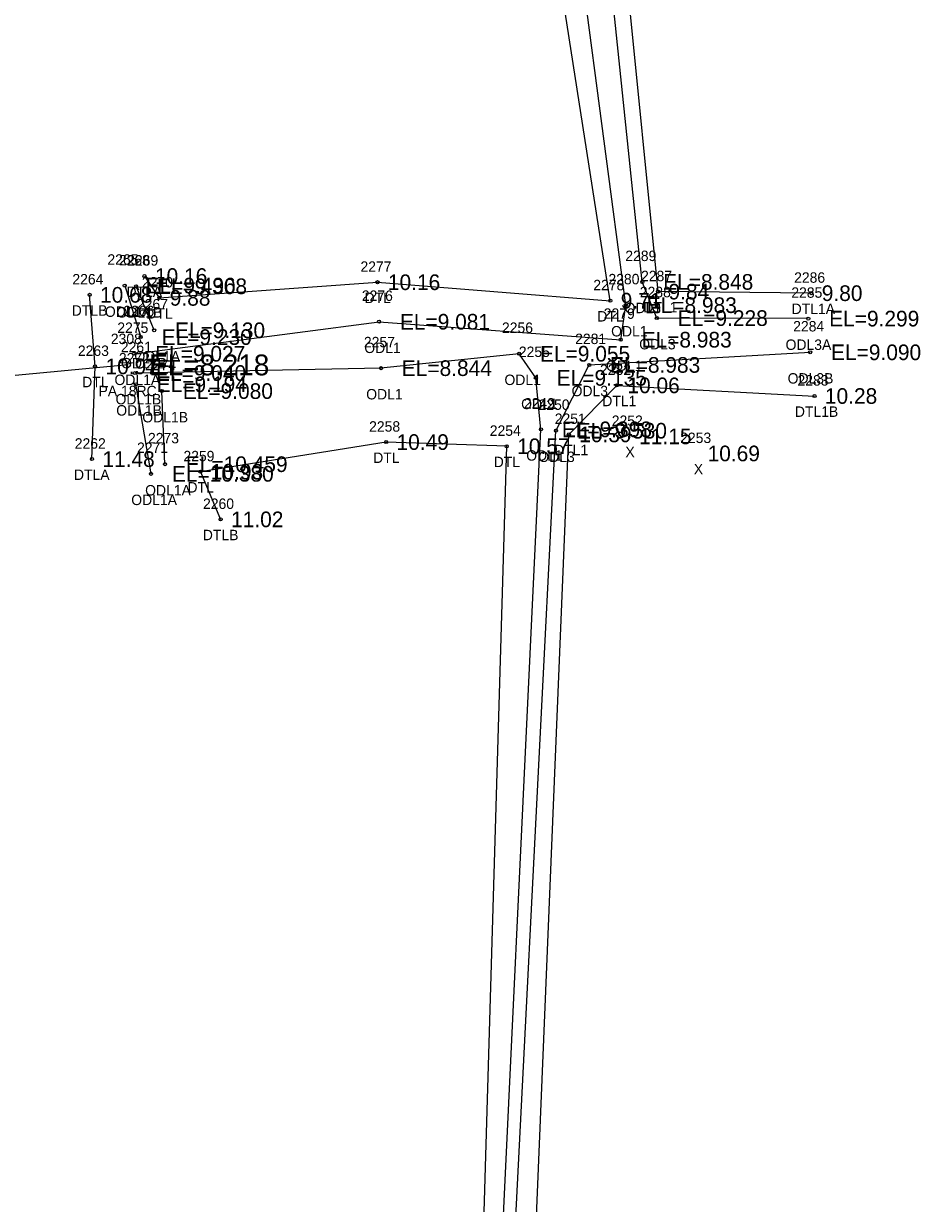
# Model space of a CAD drawing. Extents: x 2042117 to 2045853, y 303080 to 309569.
# Drawn here: x 2044366.1 to 2044452.1, y 305003.7 to 305116.8 of the extents above; entities that cross this region are included whole.
import ezdxf

# ---------------------------------------------------------------- set-up
doc = ezdxf.new("R2010")
doc.units = 0
for name, color, linetype in [('RD_EX_DR_Pipe', 7, 'Continuous'), ('RD_EX_DR_Pipe_txCode', 7, 'Continuous'), ('RD_EX_H2O', 7, 'Continuous'), ('RD_EX_H2O_txCode', 7, 'Continuous'), ('RD_EX_Misc_txCode', 7, 'Continuous'), ('RD_EX_TX_H2O_ELEV', 7, 'Continuous'), ('RD_EX_TX_Misc_ELEV', 7, 'Continuous'), ('RD_SMD_Locator', 7, 'Continuous'), ('RD_TX_Pipe_ElevEX', 7, 'Continuous')]:
    doc.layers.add(name, color=color, linetype=linetype)

msp = doc.modelspace()

# ---------------------------------------------------------------- linework, layer by layer
at = {"layer": 'RD_EX_DR_Pipe'}
msp.add_line((2044376.14, 305084.11), (2044342.61, 305081.01), dxfattribs=at)
at = {"layer": 'RD_EX_H2O'}
for p, q in [((2044375.8, 305091.72), (2044377.34, 305086.78)), ((2044378.62, 305087.43), (2044376.89, 305091.65)), ((2044378.33, 305073.67), (2044376.87, 305082.25)), ((2044379.66, 305074.59), (2044379.37, 305081.6))]:
    msp.add_line(p, q, dxfattribs=at)
for points in [[(2044376.72, 305085.18), (2044400.19, 305088.25), (2044423.37, 305086.53), (2044423.86, 305089.84), (2044419.71, 305121.34), (2044421.53, 305178.54), (2044427.38, 305280.5)], [(2044441.36, 305088.55), (2044426.83, 305088.6), (2044425.44, 305092.07), (2044422.39, 305121.28), (2044424.49, 305178.48), (2044429.93, 305280.33)], [(2044441.65, 305090.99), (2044426.95, 305091.14), (2044423.93, 305121.62), (2044425.7, 305178.46), (2044431.41, 305280.23)], [(2044377.7, 305092.63), (2044379.12, 305090.54), (2044400.04, 305092.04), (2044422.37, 305090.27), (2044417.51, 305121.46), (2044420.43, 305178.33), (2044425.99, 305280.06)], [(2044372.66, 305075.08), (2044372.96, 305083.97), (2044372.43, 305090.83)], [(2044403.47, 304870.69), (2044407.44, 304869.96), (2044408.86, 304871.35), (2044409.24, 304878.26), (2044410.13, 304929), (2044410.94, 304977.69), (2044415.72, 305077.93), (2044415.23, 305082.87), (2044413.63, 305085.18), (2044400.37, 305083.8), (2044376.8, 305083.33)], [(2044412.68, 304824.61), (2044412.4, 304834.83), (2044410.65, 304865.22), (2044410.04, 304868.77), (2044410.66, 304878.11), (2044411.75, 304929.17), (2044412.06, 304977.88), (2044417.16, 305077.8), (2044420.35, 305084.11), (2044441.54, 305085.32)], [(2044415.25, 304826.5), (2044414.68, 304834.74), (2044412.57, 304868.88), (2044413.59, 304878.38), (2044413.66, 304929.44), (2044414.3, 304978.48), (2044418.39, 305077.45), (2044423.01, 305082.15), (2044441.95, 305081.13)], [(2044408.92, 304931.32), (2044409.54, 304978.02), (2044412.44, 305076.31), (2044400.87, 305076.71), (2044383.06, 305073.87), (2044385, 305069.3)]]:
    msp.add_lwpolyline(points, dxfattribs=at)
at = {"layer": 'RD_SMD_Locator'}
for centre, radius in [((2044377.7, 305092.63), 0.15), ((2044375.8, 305091.72), 0.15), ((2044376.89, 305091.65), 0.15), ((2044400.04, 305092.04), 0.15), ((2044425.44, 305092.07), 0.15), ((2044372.43, 305090.83), 0.15), ((2044379.12, 305090.54), 0.15), ((2044422.37, 305090.27), 0.15), ((2044426.95, 305091.14), 0.15), ((2044441.65, 305090.99), 0.15), ((2044423.86, 305089.84), 0.15), ((2044400.19, 305088.25), 0.15), ((2044426.83, 305088.6), 0.15), ((2044441.36, 305088.55), 0.15), ((2044377.34, 305086.78), 0.15), ((2044378.62, 305087.43), 0.15), ((2044423.37, 305086.53), 0.15), ((2044376.72, 305085.18), 0.15), ((2044413.63, 305085.18), 0.15), ((2044441.54, 305085.32), 0.15), ((2044372.96, 305083.97), 0.15), ((2044376.14, 305084.11), 0.2), ((2044376.8, 305083.33), 0.15), ((2044400.37, 305083.8), 0.15), ((2044420.35, 305084.11), 0.15), ((2044376.87, 305082.25), 0.15), ((2044415.23, 305082.87), 0.15), ((2044423.01, 305082.15), 0.15), ((2044379.37, 305081.6), 0.15), ((2044441.95, 305081.13), 0.15), ((2044415.72, 305077.93), 0.15), ((2044417.16, 305077.8), 0.15), ((2044400.87, 305076.71), 0.15), ((2044418.39, 305077.45), 0.15), ((2044412.44, 305076.31), 0.15), ((2044372.66, 305075.08), 0.15), ((2044379.66, 305074.59), 0.15), ((2044378.33, 305073.67), 0.15), ((2044383.06, 305073.87), 0.15), ((2044385, 305069.3), 0.15)]:
    msp.add_circle(centre, radius, dxfattribs=at)

# ---------------------------------------------------------------- texts
at = {"layer": 'RD_EX_DR_Pipe_txCode'}
for s, p in [('2308', (2044374.47, 305086.11)), ('PA 18RC', (2044373.29, 305081.11))]:
    msp.add_text(s, height=1, dxfattribs=at).set_placement(p)
at = {"layer": 'RD_EX_H2O_txCode'}
for s, p in [('2265', (2044374.14, 305093.72)), ('2289', (2044423.81, 305094.07)), ('2268', (2044375.24, 305093.65)), ('2269', (2044376.04, 305093.63)), ('2277', (2044398.41, 305093.04)), ('2264', (2044370.78, 305091.83)), ('2270', (2044377.45, 305091.54)), ('2280', (2044422.19, 305091.84)), ('2287', (2044425.32, 305092.14)), ('2286', (2044440, 305091.99)), ('DTLA', (2044375.97, 305090.63)), ('2278', (2044420.74, 305091.27)), ('2288', (2044425.2, 305090.6)), ('2285', (2044439.73, 305090.55)), ('2267', (2044376.97, 305089.43)), ('2276', (2044398.54, 305090.25)), ('DTL', (2044398.8, 305090.04)), ('DTLB', (2044370.72, 305088.83)), ('ODL1A', (2044373.9, 305088.72)), ('ODL1B', (2044375.01, 305088.65)), ('2266', (2044375.66, 305088.78)), ('DTL', (2044377.87, 305088.54)), ('DTL', (2044421.12, 305088.27)), ('2279', (2044421.74, 305088.53)), ('ODL3', (2044423.74, 305089.07)), ('DTL1', (2044425.54, 305089.14)), ('DTL1A', (2044439.76, 305088.99)), ('2275', (2044375.09, 305087.18)), ('2256', (2044411.98, 305087.18)), ('2284', (2044439.91, 305087.32)), ('2257', (2044398.74, 305085.8)), ('2281', (2044419, 305086.11)), ('ODL1', (2044422.45, 305086.84)), ('2263', (2044371.31, 305084.97)), ('2261', (2044375.43, 305085.33)), ('ODL1', (2044398.78, 305085.25)), ('2255', (2044413.6, 305084.87)), ('ODL3', (2044425.14, 305085.6)), ('ODL3A', (2044439.18, 305085.55)), ('2272', (2044375.24, 305084.25)), ('ODL1B', (2044375.45, 305083.78)), ('ODL1A', (2044376.73, 305084.43)), ('2274', (2044377.74, 305083.6)), ('ODL1', (2044421.96, 305083.53)), ('2282', (2044421.38, 305083.15)), ('DTL', (2044371.72, 305081.97)), ('ODL1A', (2044374.82, 305082.18)), ('ODL1', (2044412.22, 305082.18)), ('ODL3B', (2044439.38, 305082.32)), ('2283', (2044440.32, 305082.13)), ('ODL1B', (2044374.92, 305080.33)), ('ODL1', (2044398.96, 305080.8)), ('ODL3', (2044418.66, 305081.11)), ('DTL1', (2044421.6, 305080.15)), ('ODL1B', (2044374.99, 305079.25)), ('ODL1', (2044413.82, 305079.87)), ('2249', (2044414.09, 305079.93)), ('2250', (2044415.49, 305079.8)), ('DTL1B', (2044440.07, 305079.13)), ('ODL1B', (2044377.49, 305078.6)), ('2251', (2044417.04, 305078.45)), ('2258', (2044399.24, 305077.71)), ('2254', (2044410.81, 305077.31)), ('2262', (2044371.01, 305076.08)), ('2271', (2044376.98, 305075.67)), ('2273', (2044378.03, 305076.59)), ('2259', (2044381.43, 305074.87)), ('DTL', (2044399.63, 305074.71)), ('ODL1', (2044414.31, 305074.93)), ('ODL3', (2044415.47, 305074.8)), ('DTL1', (2044416.98, 305075.45)), ('DTL', (2044411.19, 305074.31)), ('DTLA', (2044370.93, 305073.08)), ('ODL1A', (2044377.76, 305071.59)), ('DTL', (2044381.82, 305071.87)), ('ODL1A', (2044376.43, 305070.67)), ('2260', (2044383.31, 305070.3)), ('DTLB', (2044383.29, 305067.3))]:
    msp.add_text(s, height=1, dxfattribs=at).set_placement(p)
at = {"layer": 'RD_EX_Misc_txCode'}
for s, p in [('2252', (2044422.51, 305078.26)), ('2253', (2044429.07, 305076.62)), ('X', (2044423.82, 305075.26)), ('X', (2044430.38, 305073.62))]:
    msp.add_text(s, height=1, dxfattribs=at).set_placement(p)
at = {"layer": 'RD_EX_TX_H2O_ELEV'}
for s, p in [('EL=9.496', (2044377.8, 305090.97)), ('10.16', (2044378.7, 305091.88)), ('EL=9.308', (2044378.89, 305090.9)), ('10.16', (2044401.04, 305091.29)), ('EL=8.848', (2044427.44, 305091.32)), ('10.68', (2044373.43, 305090.08)), ('9.88', (2044380.12, 305089.79)), ('9.84', (2044427.95, 305090.39)), ('9.80', (2044442.65, 305090.24)), ('9.71', (2044423.37, 305089.52)), ('EL=8.983', (2044425.86, 305089.09)), ('EL=9.228', (2044428.83, 305087.85)), ('EL=9.299', (2044443.36, 305087.8)), ('EL=9.130', (2044380.62, 305086.68)), ('EL=9.081', (2044402.19, 305087.5)), ('EL=9.230', (2044379.34, 305086.03)), ('EL=8.983', (2044425.37, 305085.78)), ('EL=9.027', (2044378.72, 305084.43)), ('EL=9.055', (2044415.63, 305084.43)), ('EL=9.090', (2044443.54, 305084.57)), ('10.97', (2044373.96, 305083.22)), ('EL=8.844', (2044402.37, 305083.05)), ('EL=8.983', (2044422.35, 305083.36)), ('EL=9.040', (2044378.8, 305082.58)), ('EL=9.135', (2044417.23, 305082.12)), ('EL=9.194', (2044378.87, 305081.5)), ('EL=9.080', (2044381.37, 305080.85)), ('10.06', (2044424.01, 305081.4)), ('10.28', (2044442.95, 305080.38)), ('EL=9.398', (2044417.72, 305077.18)), ('EL=9.530', (2044419.16, 305077.05)), ('10.39', (2044419.39, 305076.7)), ('10.49', (2044401.87, 305075.96)), ('10.57', (2044413.44, 305075.56)), ('11.48', (2044373.66, 305074.33)), ('EL=10.380', (2044380.33, 305072.92)), ('EL=10.459', (2044381.66, 305073.84)), ('10.93', (2044384.06, 305073.12)), ('11.02', (2044386, 305068.55))]:
    msp.add_text(s, height=1.5, dxfattribs=at).set_placement(p)
at = {"layer": 'RD_EX_TX_Misc_ELEV'}
for s, p in [('11.15', (2044425.14, 305076.51)), ('10.69', (2044431.7, 305074.87))]:
    msp.add_text(s, height=1.5, dxfattribs=at).set_placement(p)
at = {"layer": 'RD_TX_Pipe_ElevEX'}
msp.add_text('EL=8.218', height=2, dxfattribs=at).set_placement((2044378.14, 305083.11))

doc.saveas('drawing.dxf')
